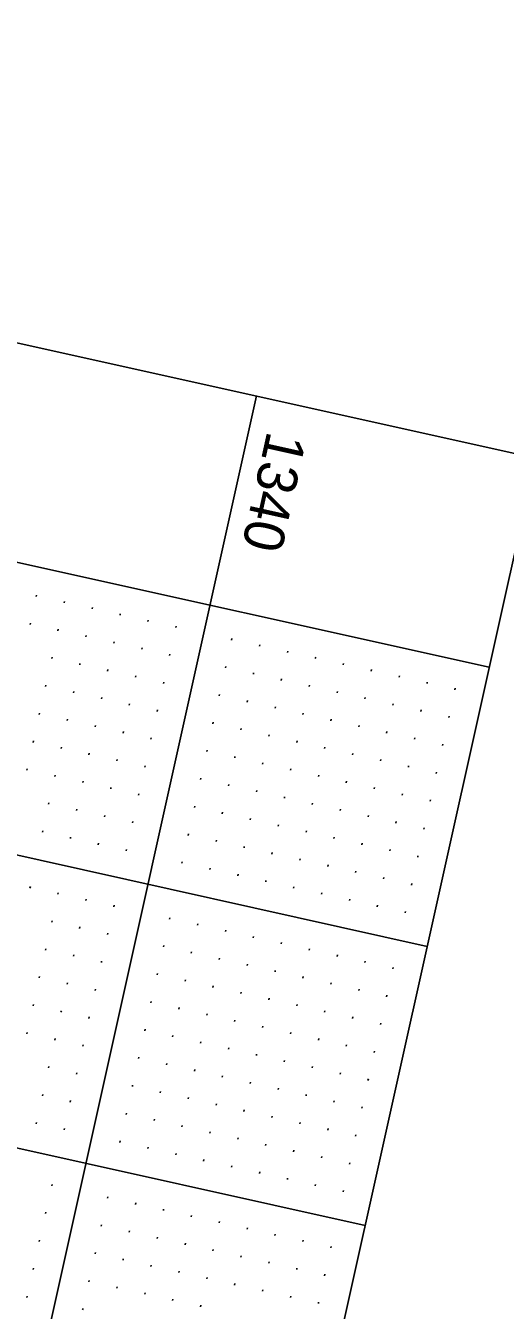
# Model space of a CAD drawing. Extents: x 2149268 to 2150830, y 142155 to 144285.
# Drawn here: x 2150117.7 to 2150201.6, y 143717.6 to 143942.3 of the extents above; entities that cross this region are included whole.
import ezdxf

# ---------------------------------------------------------------- set-up
doc = ezdxf.new("R2010")
doc.units = 0
for name, color, linetype in [('SHT_Plan_Profile_Sheet_Elev_Txt', 7, 'Continuous'), ('SHT_Profile_Grid_Major', 7, 'Continuous'), ('SHT_Profile_Grid_Minor', 7, 'Continuous'), ('SHT_Sheet_Border', 7, 'Continuous')]:
    doc.layers.add(name, color=color, linetype=linetype)

msp = doc.modelspace()

# ---------------------------------------------------------------- linework, layer by layer
at = {"layer": 'SHT_Profile_Grid_Major'}
for p, q in [((2149699.8, 143889.81), (2150187.88, 143781.28)), ((2150158.06, 143877.55), (2149816.2, 142340.1)), ((2149688.94, 143841), (2150177.02, 143732.47))]:
    msp.add_line(p, q, dxfattribs=at)
at = {"layer": 'SHT_Profile_Grid_Minor'}
for p, q in [((2150119.58, 143842.7), (2150119.52, 143842.45)), ((2150124.46, 143841.61), (2150124.41, 143841.37)), ((2150129.34, 143840.52), (2150129.29, 143840.28)), ((2150134.22, 143839.44), (2150134.17, 143839.2)), ((2150139.1, 143838.35), (2150139.05, 143838.11)), ((2150118.49, 143837.81), (2150118.44, 143837.57)), ((2150123.37, 143836.73), (2150123.32, 143836.49)), ((2150143.98, 143837.27), (2150143.93, 143837.02)), ((2150128.26, 143835.64), (2150128.2, 143835.4)), ((2150133.14, 143834.56), (2150133.08, 143834.31)), ((2150153.74, 143835.1), (2150153.69, 143834.85)), ((2150158.63, 143834.01), (2150158.57, 143833.77)), ((2150122.29, 143831.85), (2150122.24, 143831.6)), ((2150138.02, 143833.47), (2150137.96, 143833.23)), ((2150142.9, 143832.39), (2150142.84, 143832.14)), ((2150163.51, 143832.93), (2150163.45, 143832.68)), ((2150168.39, 143831.84), (2150168.33, 143831.6)), ((2150127.17, 143830.76), (2150127.12, 143830.52)), ((2150132.05, 143829.68), (2150132, 143829.43)), ((2150152.66, 143830.22), (2150152.61, 143829.97)), ((2150157.54, 143829.13), (2150157.49, 143828.89)), ((2150173.27, 143830.76), (2150173.21, 143830.51)), ((2150178.15, 143829.67), (2150178.09, 143829.43)), ((2150121.2, 143826.97), (2150121.15, 143826.72)), ((2150136.93, 143828.59), (2150136.88, 143828.35)), ((2150141.81, 143827.51), (2150141.76, 143827.26)), ((2150162.42, 143828.05), (2150162.37, 143827.8)), ((2150167.3, 143826.96), (2150167.25, 143826.72)), ((2150183.03, 143828.59), (2150182.98, 143828.34)), ((2150187.91, 143827.5), (2150187.86, 143827.26)), ((2150126.08, 143825.88), (2150126.03, 143825.64)), ((2150130.97, 143824.8), (2150130.91, 143824.55)), ((2150151.57, 143825.34), (2150151.52, 143825.09)), ((2150172.18, 143825.88), (2150172.13, 143825.63)), ((2150177.06, 143824.79), (2150177.01, 143824.55)), ((2150192.79, 143826.42), (2150192.74, 143826.17)), ((2150135.85, 143823.71), (2150135.79, 143823.47)), ((2150140.73, 143822.63), (2150140.67, 143822.38)), ((2150156.46, 143824.25), (2150156.4, 143824.01)), ((2150161.34, 143823.17), (2150161.28, 143822.92)), ((2150181.94, 143823.71), (2150181.89, 143823.46)), ((2150186.83, 143822.62), (2150186.77, 143822.38)), ((2150120.12, 143822.09), (2150120.06, 143821.84)), ((2150125, 143821), (2150124.95, 143820.76)), ((2150150.49, 143820.46), (2150150.43, 143820.21)), ((2150166.22, 143822.08), (2150166.16, 143821.84)), ((2150171.1, 143821), (2150171.04, 143820.75)), ((2150191.71, 143821.54), (2150191.65, 143821.29)), ((2150129.88, 143819.92), (2150129.83, 143819.67)), ((2150134.76, 143818.83), (2150134.71, 143818.59)), ((2150155.37, 143819.37), (2150155.32, 143819.13)), ((2150160.25, 143818.29), (2150160.2, 143818.04)), ((2150175.98, 143819.91), (2150175.92, 143819.67)), ((2150180.86, 143818.83), (2150180.8, 143818.58)), ((2150119.03, 143817.21), (2150118.98, 143816.96)), ((2150123.91, 143816.12), (2150123.86, 143815.88)), ((2150139.64, 143817.75), (2150139.59, 143817.5)), ((2150149.4, 143815.58), (2150149.35, 143815.33)), ((2150165.13, 143817.2), (2150165.08, 143816.96)), ((2150170.01, 143816.11), (2150169.96, 143815.87)), ((2150185.74, 143817.74), (2150185.69, 143817.5)), ((2150190.62, 143816.65), (2150190.57, 143816.41)), ((2150128.8, 143815.04), (2150128.74, 143814.79)), ((2150133.68, 143813.95), (2150133.62, 143813.71)), ((2150154.28, 143814.49), (2150154.23, 143814.25)), ((2150159.17, 143813.4), (2150159.11, 143813.16)), ((2150174.89, 143815.03), (2150174.84, 143814.79)), ((2150179.77, 143813.94), (2150179.72, 143813.7)), ((2150117.95, 143812.33), (2150117.89, 143812.08)), ((2150122.83, 143811.24), (2150122.77, 143811)), ((2150138.56, 143812.86), (2150138.5, 143812.62)), ((2150164.05, 143812.32), (2150163.99, 143812.08)), ((2150168.93, 143811.23), (2150168.87, 143810.99)), ((2150184.65, 143812.86), (2150184.6, 143812.61)), ((2150189.54, 143811.77), (2150189.48, 143811.53)), ((2150127.71, 143810.15), (2150127.66, 143809.91)), ((2150132.59, 143809.07), (2150132.54, 143808.83)), ((2150148.32, 143810.69), (2150148.26, 143810.45)), ((2150153.2, 143809.61), (2150153.14, 143809.37)), ((2150173.81, 143810.15), (2150173.75, 143809.9)), ((2150178.69, 143809.06), (2150178.63, 143808.82)), ((2150137.47, 143807.98), (2150137.42, 143807.74)), ((2150158.08, 143808.52), (2150158.03, 143808.28)), ((2150162.96, 143807.44), (2150162.91, 143807.19)), ((2150183.57, 143807.98), (2150183.51, 143807.73)), ((2150188.45, 143806.89), (2150188.4, 143806.65)), ((2150121.74, 143806.36), (2150121.69, 143806.12)), ((2150126.62, 143805.27), (2150126.57, 143805.03)), ((2150147.23, 143805.81), (2150147.18, 143805.57)), ((2150152.11, 143804.73), (2150152.06, 143804.48)), ((2150167.84, 143806.35), (2150167.79, 143806.11)), ((2150172.72, 143805.27), (2150172.67, 143805.02)), ((2150131.51, 143804.19), (2150131.45, 143803.94)), ((2150136.39, 143803.1), (2150136.33, 143802.86)), ((2150156.99, 143803.64), (2150156.94, 143803.4)), ((2150161.88, 143802.56), (2150161.82, 143802.31)), ((2150177.6, 143804.18), (2150177.55, 143803.94)), ((2150182.48, 143803.1), (2150182.43, 143802.85)), ((2150120.66, 143801.48), (2150120.6, 143801.23)), ((2150125.54, 143800.39), (2150125.49, 143800.15)), ((2150146.15, 143800.93), (2150146.09, 143800.69)), ((2150151.03, 143799.85), (2150150.97, 143799.6)), ((2150166.76, 143801.47), (2150166.7, 143801.23)), ((2150171.64, 143800.39), (2150171.58, 143800.14)), ((2150187.36, 143802.01), (2150187.31, 143801.77)), ((2150130.42, 143799.31), (2150130.37, 143799.06)), ((2150135.3, 143798.22), (2150135.25, 143797.98)), ((2150155.91, 143798.76), (2150155.86, 143798.52)), ((2150160.79, 143797.68), (2150160.74, 143797.43)), ((2150176.52, 143799.3), (2150176.46, 143799.06)), ((2150181.4, 143798.22), (2150181.34, 143797.97)), ((2150145.06, 143796.05), (2150145.01, 143795.81)), ((2150165.67, 143796.59), (2150165.62, 143796.35)), ((2150170.55, 143795.51), (2150170.5, 143795.26)), ((2150186.28, 143797.13), (2150186.23, 143796.89)), ((2150149.94, 143794.97), (2150149.89, 143794.72)), ((2150154.82, 143793.88), (2150154.77, 143793.64)), ((2150175.43, 143794.42), (2150175.38, 143794.18)), ((2150180.31, 143793.34), (2150180.26, 143793.09)), ((2150118.49, 143791.72), (2150118.43, 143791.47)), ((2150159.7, 143792.8), (2150159.65, 143792.55)), ((2150164.59, 143791.71), (2150164.53, 143791.47)), ((2150185.19, 143792.25), (2150185.14, 143792.01)), ((2150123.37, 143790.63), (2150123.31, 143790.39)), ((2150128.25, 143789.55), (2150128.2, 143789.3)), ((2150169.47, 143790.63), (2150169.41, 143790.38)), ((2150174.35, 143789.54), (2150174.29, 143789.3)), ((2150133.13, 143788.46), (2150133.08, 143788.22)), ((2150179.23, 143788.46), (2150179.17, 143788.21)), ((2150184.11, 143787.37), (2150184.05, 143787.13)), ((2150122.28, 143785.75), (2150122.23, 143785.51)), ((2150127.16, 143784.67), (2150127.11, 143784.42)), ((2150142.89, 143786.29), (2150142.84, 143786.05)), ((2150147.77, 143785.21), (2150147.72, 143784.96)), ((2150152.65, 143784.12), (2150152.6, 143783.88)), ((2150132.05, 143783.58), (2150131.99, 143783.34)), ((2150157.53, 143783.03), (2150157.48, 143782.79)), ((2150162.42, 143781.95), (2150162.36, 143781.71)), ((2150121.2, 143780.87), (2150121.14, 143780.63)), ((2150126.08, 143779.78), (2150126.02, 143779.54)), ((2150141.81, 143781.41), (2150141.75, 143781.17)), ((2150146.69, 143780.32), (2150146.63, 143780.08)), ((2150167.3, 143780.86), (2150167.24, 143780.62)), ((2150172.18, 143779.78), (2150172.12, 143779.53)), ((2150130.96, 143778.7), (2150130.91, 143778.46)), ((2150151.57, 143779.24), (2150151.51, 143778.99)), ((2150156.45, 143778.15), (2150156.39, 143777.91)), ((2150177.06, 143778.69), (2150177, 143778.45)), ((2150181.94, 143777.61), (2150181.88, 143777.36)), ((2150120.11, 143775.99), (2150120.06, 143775.75)), ((2150140.72, 143776.53), (2150140.67, 143776.28)), ((2150145.6, 143775.44), (2150145.55, 143775.2)), ((2150161.33, 143777.07), (2150161.28, 143776.82)), ((2150166.21, 143775.98), (2150166.16, 143775.74)), ((2150124.99, 143774.9), (2150124.94, 143774.66)), ((2150129.87, 143773.82), (2150129.82, 143773.57)), ((2150150.48, 143774.36), (2150150.43, 143774.11)), ((2150155.36, 143773.27), (2150155.31, 143773.03)), ((2150171.09, 143774.9), (2150171.04, 143774.65)), ((2150175.97, 143773.81), (2150175.92, 143773.57)), ((2150119.03, 143771.11), (2150118.97, 143770.86)), ((2150139.64, 143771.65), (2150139.58, 143771.4)), ((2150160.24, 143772.19), (2150160.19, 143771.94)), ((2150165.13, 143771.1), (2150165.07, 143770.86)), ((2150180.85, 143772.73), (2150180.8, 143772.48)), ((2150123.91, 143770.02), (2150123.85, 143769.78)), ((2150128.79, 143768.94), (2150128.74, 143768.69)), ((2150144.52, 143770.56), (2150144.46, 143770.32)), ((2150149.4, 143769.48), (2150149.34, 143769.23)), ((2150154.28, 143768.39), (2150154.22, 143768.15)), ((2150170.01, 143770.02), (2150169.95, 143769.77)), ((2150174.89, 143768.93), (2150174.83, 143768.69)), ((2150117.94, 143766.23), (2150117.89, 143765.98)), ((2150138.55, 143766.77), (2150138.5, 143766.52)), ((2150159.16, 143767.31), (2150159.11, 143767.06)), ((2150164.04, 143766.22), (2150163.99, 143765.98)), ((2150179.77, 143767.85), (2150179.71, 143767.6)), ((2150122.82, 143765.14), (2150122.77, 143764.9)), ((2150127.7, 143764.06), (2150127.65, 143763.81)), ((2150143.43, 143765.68), (2150143.38, 143765.44)), ((2150148.31, 143764.6), (2150148.26, 143764.35)), ((2150168.92, 143765.14), (2150168.87, 143764.89)), ((2150173.8, 143764.05), (2150173.75, 143763.81)), ((2150137.47, 143761.89), (2150137.41, 143761.64)), ((2150153.19, 143763.51), (2150153.14, 143763.27)), ((2150158.07, 143762.43), (2150158.02, 143762.18)), ((2150178.68, 143762.97), (2150178.63, 143762.72)), ((2150121.74, 143760.26), (2150121.68, 143760.02)), ((2150142.35, 143760.8), (2150142.29, 143760.56)), ((2150147.23, 143759.72), (2150147.17, 143759.47)), ((2150162.95, 143761.34), (2150162.9, 143761.1)), ((2150167.84, 143760.26), (2150167.78, 143760.01)), ((2150126.62, 143759.18), (2150126.56, 143758.93)), ((2150152.11, 143758.63), (2150152.05, 143758.39)), ((2150156.99, 143757.55), (2150156.93, 143757.3)), ((2150172.72, 143759.17), (2150172.66, 143758.93)), ((2150177.6, 143758.09), (2150177.54, 143757.84)), ((2150120.65, 143755.38), (2150120.6, 143755.14)), ((2150136.38, 143757.01), (2150136.33, 143756.76)), ((2150141.26, 143755.92), (2150141.21, 143755.68)), ((2150161.87, 143756.46), (2150161.82, 143756.22)), ((2150166.75, 143755.37), (2150166.7, 143755.13)), ((2150125.53, 143754.3), (2150125.48, 143754.05)), ((2150146.14, 143754.84), (2150146.09, 143754.59)), ((2150151.02, 143753.75), (2150150.97, 143753.51)), ((2150155.9, 143752.66), (2150155.85, 143752.42)), ((2150171.63, 143754.29), (2150171.58, 143754.05)), ((2150176.51, 143753.2), (2150176.46, 143752.96)), ((2150119.57, 143750.5), (2150119.51, 143750.26)), ((2150135.3, 143752.12), (2150135.24, 143751.88)), ((2150140.18, 143751.04), (2150140.12, 143750.8)), ((2150160.78, 143751.58), (2150160.73, 143751.34)), ((2150165.67, 143750.49), (2150165.61, 143750.25)), ((2150124.45, 143749.41), (2150124.39, 143749.17)), ((2150145.06, 143749.95), (2150145, 143749.71)), ((2150149.94, 143748.87), (2150149.88, 143748.62)), ((2150170.55, 143749.41), (2150170.49, 143749.16)), ((2150175.43, 143748.32), (2150175.37, 143748.08)), ((2150134.21, 143747.24), (2150134.16, 143747)), ((2150139.09, 143746.16), (2150139.04, 143745.91)), ((2150154.82, 143747.78), (2150154.76, 143747.54)), ((2150159.7, 143746.7), (2150159.64, 143746.45)), ((2150143.97, 143745.07), (2150143.92, 143744.83)), ((2150148.85, 143743.99), (2150148.8, 143743.74)), ((2150164.58, 143745.61), (2150164.53, 143745.37)), ((2150169.46, 143744.53), (2150169.41, 143744.28)), ((2150153.73, 143742.9), (2150153.68, 143742.66)), ((2150158.61, 143741.82), (2150158.56, 143741.57)), ((2150174.34, 143743.44), (2150174.29, 143743.2)), ((2150122.28, 143739.65), (2150122.22, 143739.41)), ((2150163.49, 143740.73), (2150163.44, 143740.49)), ((2150168.38, 143739.65), (2150168.32, 143739.4)), ((2150132.04, 143737.48), (2150131.98, 143737.24)), ((2150173.26, 143738.56), (2150173.2, 143738.32)), ((2150121.19, 143734.77), (2150121.14, 143734.53)), ((2150136.92, 143736.4), (2150136.87, 143736.15)), ((2150141.8, 143735.31), (2150141.75, 143735.07)), ((2150130.95, 143732.6), (2150130.9, 143732.36)), ((2150146.68, 143734.23), (2150146.63, 143733.98)), ((2150151.56, 143733.14), (2150151.51, 143732.9)), ((2150135.83, 143731.52), (2150135.78, 143731.27)), ((2150140.72, 143730.43), (2150140.66, 143730.19)), ((2150156.44, 143732.06), (2150156.39, 143731.81)), ((2150161.32, 143730.97), (2150161.27, 143730.73)), ((2150120.11, 143729.89), (2150120.05, 143729.65)), ((2150145.6, 143729.35), (2150145.54, 143729.1)), ((2150150.48, 143728.26), (2150150.42, 143728.02)), ((2150166.2, 143729.89), (2150166.15, 143729.64)), ((2150171.09, 143728.8), (2150171.03, 143728.56)), ((2150129.87, 143727.72), (2150129.81, 143727.48)), ((2150134.75, 143726.64), (2150134.7, 143726.39)), ((2150155.36, 143727.18), (2150155.3, 143726.93)), ((2150160.24, 143726.09), (2150160.18, 143725.85)), ((2150119.02, 143725.01), (2150118.97, 143724.77)), ((2150139.63, 143725.55), (2150139.58, 143725.31)), ((2150144.51, 143724.46), (2150144.46, 143724.22)), ((2150165.12, 143725), (2150165.07, 143724.76)), ((2150170, 143723.92), (2150169.95, 143723.68)), ((2150128.78, 143722.84), (2150128.73, 143722.6)), ((2150133.66, 143721.75), (2150133.61, 143721.51)), ((2150149.39, 143723.38), (2150149.34, 143723.14)), ((2150154.27, 143722.29), (2150154.22, 143722.05)), ((2150159.15, 143721.21), (2150159.1, 143720.97)), ((2150117.94, 143720.13), (2150117.88, 143719.89)), ((2150138.55, 143720.67), (2150138.49, 143720.43)), ((2150143.43, 143719.58), (2150143.37, 143719.34)), ((2150164.03, 143720.12), (2150163.98, 143719.88)), ((2150168.91, 143719.04), (2150168.86, 143718.79)), ((2150127.7, 143717.96), (2150127.64, 143717.72)), ((2150148.31, 143718.5), (2150148.25, 143718.25))]:
    msp.add_line(p, q, dxfattribs=at)
at = {"layer": 'SHT_Sheet_Border'}
for p, q in [((2149710.65, 143938.62), (2150198.73, 143830.09)), ((2150206.87, 143866.7), (2149865.01, 142329.24))]:
    msp.add_line(p, q, dxfattribs=at)
msp.add_lwpolyline([(2150726.67, 143751.11), (2150384.81, 142213.66), (2149359.84, 142441.57), (2149701.71, 143979.02)], close=True, dxfattribs=at)

# ---------------------------------------------------------------- texts
at = {"layer": 'SHT_Plan_Profile_Sheet_Elev_Txt'}
msp.add_text('1340', height=7, rotation=257.4638, dxfattribs=at).set_placement((2150159.97, 143871.6))

doc.saveas('drawing.dxf')
